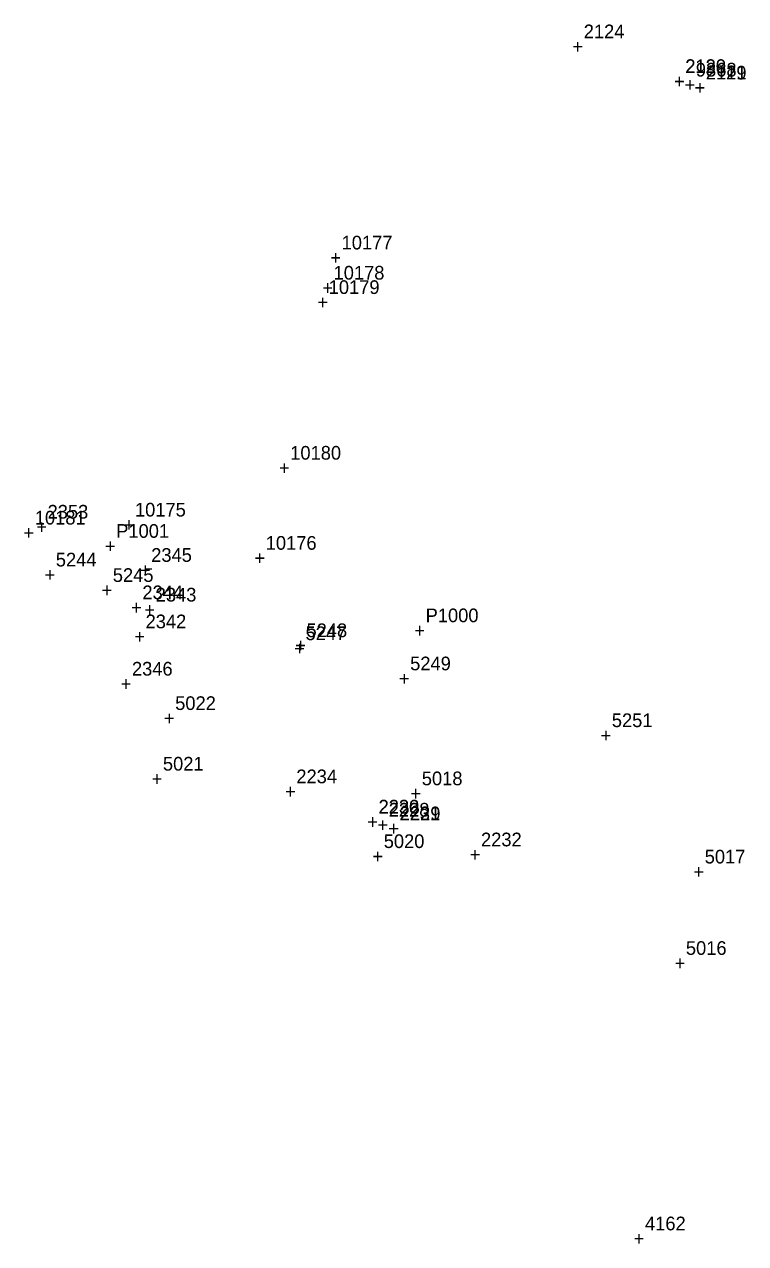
# Model space of a CAD drawing. Extents: x 1136220 to 1137808, y 528804 to 531215.
# Drawn here: x 1136972.2 to 1137104, y 529122.9 to 529345.7 of the extents above; entities that cross this region are included whole.
import ezdxf

# ---------------------------------------------------------------- set-up
doc = ezdxf.new("R2010")
doc.units = 0
for name, color, linetype in [('S_Buildings', 7, 'Continuous'), ('S_Buildings_SillElevation', 7, 'Continuous'), ('S_Curb_Type_1', 7, 'Continuous'), ('S_Drainage_Culvert_Top', 7, 'Continuous'), ('S_Drainage_Invert', 7, 'Continuous'), ('S_Property_IronPipeFound', 7, 'Continuous'), ('S_Roadway_Centerline', 7, 'Continuous'), ('S_Roadway_Edge_Pavement', 7, 'Continuous'), ('S_Utilities_GuyWire3', 7, 'Continuous'), ('S_Utilities_Pole_Joint', 7, 'Continuous'), ('S_Utilities_UG_Gas_Line', 7, 'Continuous'), ('S_Utilities_UG_Sanitary_MH', 7, 'Continuous'), ('S_Utilities_UG_Water_Gate', 7, 'Continuous'), ('S_Utilities_UG_Water_Line', 7, 'Continuous')]:
    doc.layers.add(name, color=color, linetype=linetype)

msp = doc.modelspace()

# ---------------------------------------------------------------- texts
at = {"layer": 'S_Buildings'}
for s, p in [('10177', (1137030.19, 529304.58)), ('+', (1137028.13, 529301.83)), ('2353', (1136976.45, 529255.4)), ('10175', (1136992.42, 529255.78)), ('10181', (1136974.11, 529254.32)), ('+', (1136990.36, 529253.03)), ('+', (1136972.04, 529251.57)), ('+', (1136974.39, 529252.65)), ('10176', (1137016.32, 529249.71)), ('+', (1137014.26, 529246.96))]:
    msp.add_text(s, height=2.5, dxfattribs=at).set_placement(p)
at = {"layer": 'S_Buildings_SillElevation'}
for s, p in [('10178', (1137028.72, 529299.07)), ('+', (1137026.66, 529296.32)), ('10179', (1137027.83, 529296.44)), ('+', (1137025.77, 529293.69)), ('10180', (1137020.8, 529266.17)), ('+', (1137018.74, 529263.42)), ('4162', (1137085.65, 529125.36)), ('+', (1137083.58, 529122.61))]:
    msp.add_text(s, height=2.5, dxfattribs=at).set_placement(p)
at = {"layer": 'S_Curb_Type_1'}
for s, p in [('5244', (1136977.95, 529246.65)), ('+', (1136975.89, 529243.9)), ('5245', (1136988.37, 529243.83)), ('+', (1136986.31, 529241.08)), ('5248', (1137023.77, 529233.74)), ('+', (1137021.71, 529231))]:
    msp.add_text(s, height=2.5, dxfattribs=at).set_placement(p)
at = {"layer": 'S_Drainage_Culvert_Top'}
for s, p in [('2124', (1137074.45, 529343.16)), ('+', (1137072.38, 529340.41)), ('2123', (1137093.03, 529336.79)), ('2121', (1137096.76, 529335.66)), ('+', (1137090.97, 529334.04)), ('+', (1137094.7, 529332.91)), ('2234', (1137021.92, 529207.05)), ('+', (1137019.86, 529204.3)), ('2233', (1137036.96, 529201.5)), ('2231', (1137040.77, 529200.29)), ('+', (1137034.9, 529198.75)), ('+', (1137038.71, 529197.54)), ('2232', (1137055.67, 529195.52)), ('+', (1137053.61, 529192.77))]:
    msp.add_text(s, height=2.5, dxfattribs=at).set_placement(p)
at = {"layer": 'S_Drainage_Invert'}
for s, p in [('2120', (1137093, 529336.82)), ('2119', (1137096.76, 529335.63)), ('+', (1137090.94, 529334.07)), ('+', (1137094.7, 529332.88)), ('2230', (1137036.94, 529201.52)), ('2229', (1137040.82, 529200.28)), ('+', (1137034.88, 529198.77)), ('+', (1137038.76, 529197.53))]:
    msp.add_text(s, height=2.5, dxfattribs=at).set_placement(p)
at = {"layer": 'S_Property_IronPipeFound'}
for s, p in [('P1001', (1136988.99, 529251.89)), ('+', (1136986.93, 529249.14)), ('P1000', (1137045.55, 529236.47)), ('+', (1137043.49, 529233.72))]:
    msp.add_text(s, height=2.5, dxfattribs=at).set_placement(p)
at = {"layer": 'S_Roadway_Centerline'}
for s, p in [('5022', (1136999.77, 529220.43)), ('+', (1136997.71, 529217.68)), ('5018', (1137044.85, 529206.68)), ('+', (1137042.78, 529203.93)), ('5017', (1137096.56, 529192.39)), ('+', (1137094.5, 529189.64))]:
    msp.add_text(s, height=2.5, dxfattribs=at).set_placement(p)
at = {"layer": 'S_Roadway_Edge_Pavement'}
for s, p in [('5247', (1137023.59, 529233.19)), ('+', (1137021.53, 529230.44)), ('5249', (1137042.72, 529227.68)), ('+', (1137040.66, 529224.93)), ('5251', (1137079.58, 529217.3)), ('+', (1137077.52, 529214.55)), ('5021', (1136997.53, 529209.36)), ('+', (1136995.47, 529206.61)), ('5020', (1137037.89, 529195.21)), ('+', (1137035.83, 529192.46)), ('5016', (1137093.12, 529175.69)), ('+', (1137091.06, 529172.94))]:
    msp.add_text(s, height=2.5, dxfattribs=at).set_placement(p)
at = {"layer": 'S_Utilities_GuyWire3'}
for s, p in [('2345', (1136995.39, 529247.5)), ('+', (1136993.33, 529244.75))]:
    msp.add_text(s, height=2.5, dxfattribs=at).set_placement(p)
at = {"layer": 'S_Utilities_Pole_Joint'}
for s, p in [('2344', (1136993.78, 529240.67)), ('+', (1136991.72, 529237.92))]:
    msp.add_text(s, height=2.5, dxfattribs=at).set_placement(p)
at = {"layer": 'S_Utilities_UG_Gas_Line'}
for s, p in [('2342', (1136994.36, 529235.36)), ('+', (1136992.3, 529232.61))]:
    msp.add_text(s, height=2.5, dxfattribs=at).set_placement(p)
at = {"layer": 'S_Utilities_UG_Sanitary_MH'}
for s, p in [('9368', (1137094.94, 529336.17)), ('+', (1137092.88, 529333.42)), ('2228', (1137038.8, 529200.95)), ('+', (1137036.74, 529198.2))]:
    msp.add_text(s, height=2.5, dxfattribs=at).set_placement(p)
at = {"layer": 'S_Utilities_UG_Water_Gate'}
for s, p in [('2343', (1136996.21, 529240.25)), ('+', (1136994.14, 529237.5))]:
    msp.add_text(s, height=2.5, dxfattribs=at).set_placement(p)
at = {"layer": 'S_Utilities_UG_Water_Line'}
for s, p in [('2346', (1136991.87, 529226.72)), ('+', (1136989.81, 529223.97))]:
    msp.add_text(s, height=2.5, dxfattribs=at).set_placement(p)

doc.saveas('drawing.dxf')
